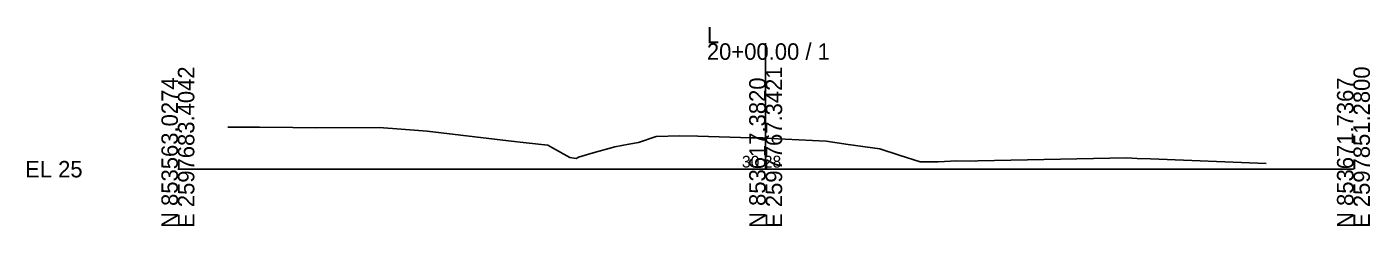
# Model space of a CAD drawing. Extents: x -26 to 1203, y -10 to 9526.
# Drawn here: x 974.3 to 1202.8, y -9.7 to 24.2 of the extents above; entities that cross this region are included whole.
import ezdxf

# ---------------------------------------------------------------- set-up
doc = ezdxf.new("R2010")
doc.units = 0
for name, color, linetype in [('Exist Cross Section Cell', 7, 'Continuous'), ('Exist XS Center Line Elevation Label', 7, 'Continuous'), ('Exist XS Ground Line', 7, 'Continuous')]:
    doc.layers.add(name, color=color, linetype=linetype)

msp = doc.modelspace()

# ---------------------------------------------------------------- linework, layer by layer
at = {"layer": 'Exist Cross Section Cell'}
for p, q in [((1100, 0), (1100, 21.42)), ((1000, 0), (1100, 0)), ((1100, 0), (1200, 0))]:
    msp.add_line(p, q, dxfattribs=at)
at = {"layer": 'Exist XS Ground Line'}
for p, q in [((1008.51, 7.13), (1013.87, 7.14)), ((1013.87, 7.14), (1019.53, 7.12)), ((1019.53, 7.12), (1023.35, 7.05)), ((1023.35, 7.05), (1034.23, 7.11)), ((1034.23, 7.11), (1038.01, 6.8)), ((1038.01, 6.8), (1042.4, 6.49)), ((1042.4, 6.49), (1056.25, 4.82)), ((1056.25, 4.82), (1059.28, 4.47)), ((1078.35, 4.55), (1081.38, 5.56)), ((1081.38, 5.56), (1085.38, 5.69)), ((1085.38, 5.69), (1088.45, 5.61)), ((1088.45, 5.61), (1097.55, 5.36)), ((1097.55, 5.36), (1099.51, 5.31)), ((1099.51, 5.31), (1100, 5.28)), ((1100, 5.28), (1101, 5.23)), ((1101, 5.23), (1110.3, 4.76)), ((1110.3, 4.76), (1114.04, 4.22)), ((1059.28, 4.47), (1062.93, 4.11)), ((1062.93, 4.11), (1063.75, 3.65)), ((1063.75, 3.65), (1066.71, 1.97)), ((1068.16, 2.03), (1070.66, 2.76)), ((1070.66, 2.76), (1074.35, 3.8)), ((1074.35, 3.8), (1076.7, 4.27)), ((1076.7, 4.27), (1078.35, 4.55)), ((1114.04, 4.22), (1119.45, 3.47)), ((1119.45, 3.47), (1122.74, 2.38)), ((1122.74, 2.38), (1126.26, 1.27)), ((1066.71, 1.97), (1067.75, 1.81)), ((1067.75, 1.81), (1068.16, 2.03)), ((1126.26, 1.27), (1129.32, 1.27)), ((1129.32, 1.27), (1132.53, 1.41)), ((1132.53, 1.41), (1135.62, 1.37)), ((1135.62, 1.37), (1136.08, 1.4)), ((1136.08, 1.4), (1161.39, 1.91)), ((1161.39, 1.91), (1163.21, 1.82)), ((1163.21, 1.82), (1165.46, 1.78)), ((1165.46, 1.78), (1185.13, 0.99))]:
    msp.add_line(p, q, dxfattribs=at)

# ---------------------------------------------------------------- texts
at = {"layer": 'Exist Cross Section Cell'}
for s, p in [('L', (1090, 21.42)), ('20+00.00 / 1', (1090, 18.62)), ('EL 25', (974, -1.4))]:
    msp.add_text(s, height=2.8, dxfattribs=at).set_placement(p)
for s, p in [('E 2597683.4042', (1002.8, -10)), ('E 2597767.3421', (1102.8, -10)), ('E 2597851.2800', (1202.8, -10)), ('N 853563.0274', (1000, -10)), ('N 853617.3820', (1100, -10)), ('N 853671.7367', (1200, -10))]:
    msp.add_text(s, height=2.8, rotation=90, dxfattribs=at).set_placement(p)
at = {"layer": 'Exist XS Center Line Elevation Label'}
msp.add_text('30.28', height=2, dxfattribs=at).set_placement((1095.96, 0.28))

doc.saveas('drawing.dxf')
